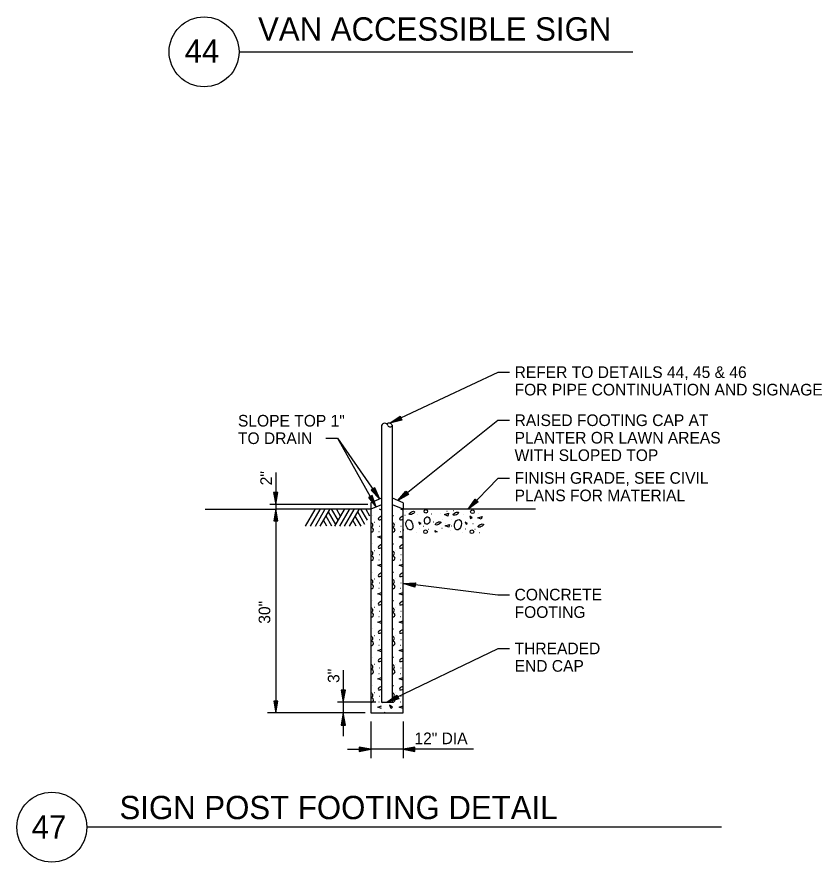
# Model space of a CAD drawing. Extents: x -121933 to -117742, y -103160 to -100084.
# Drawn here: x -118837.9 to -118423.2, y -102020 to -101584.8 of the extents above; entities that cross this region are included whole.
import ezdxf

# ---------------------------------------------------------------- set-up
doc = ezdxf.new("R2010")
doc.units = 0
for name, color, linetype in [('22', 7, 'Continuous'), ('C-TEXT', 7, 'Continuous'), ('Misc CnstDet(22)', 7, 'Continuous'), ('S-FNDN-PILE', 7, 'Continuous')]:
    doc.layers.add(name, color=color, linetype=linetype)

# ---------------------------------------------------------------- blocks, each defined once
blk = doc.blocks.new('ARROW')
at = {"layer": 'S-FNDN-PILE'}
blk.add_lwpolyline([(-0.00208, 0.00037), (-0.00208, -0.00037), (0, 0), (-0.00208, 0.00037), (-0.00198, 0), (-0.00202, -0.00027), (-0.00045, 0.00002), (-0.00202, 0.0003), (-0.00192, 0), (-0.00192, -0.00017), (-0.00083, 0.00002), (-0.00188, 0.0002), (-0.00187, -0.00012), (-0.00122, 0), (-0.00182, 0.0001), (-0.00177, -0.00005), (-0.00155, 0), (-0.00208, 0)], dxfattribs=at)

msp = doc.modelspace()

# ---------------------------------------------------------------- linework, layer by layer
at = {"layer": '22'}
for p, q in [((-118650.09, -101795.18), (-118650.09, -101937.62)), ((-118644.55, -101937.62), (-118644.55, -101795.18)), ((-118704.57, -101819.4), (-118704.57, -101850.28)), ((-118644.55, -101835.28), (-118644.55, -101819.58)), ((-118650.09, -101832.64), (-118655.6, -101834.9)), ((-118639.03, -101834.9), (-118644.55, -101832.64)), ((-118740.9, -101838.28), (-118704.79, -101838.28)), ((-118657.1, -101835.86), (-118707.57, -101835.86)), ((-118655.6, -101838.28), (-118704.79, -101838.28)), ((-118704.57, -101838.28), (-118704.57, -101943.14)), ((-118689.21, -101846.95), (-118684.27, -101838.38)), ((-118686.68, -101846.95), (-118681.77, -101838.4)), ((-118684.17, -101846.92), (-118679.29, -101838.43)), ((-118681.69, -101846.92), (-118676.76, -101838.43)), ((-118672.43, -101843.92), (-118675.65, -101838.4)), ((-118674.18, -101846.95), (-118669.22, -101838.38)), ((-118671.19, -101841.77), (-118673.16, -101838.38)), ((-118671.64, -101846.95), (-118666.69, -101838.38)), ((-118669.11, -101846.95), (-118664.18, -101838.38)), ((-118666.59, -101846.95), (-118661.65, -101838.38)), ((-118657.38, -101843.92), (-118660.57, -101838.4)), ((-118656.14, -101841.77), (-118658.09, -101838.38)), ((-118655.6, -101834.9), (-118655.6, -101838.28)), ((-118650.09, -101836.02), (-118655.6, -101838.28)), ((-118655.6, -101838.28), (-118655.6, -101943.14)), ((-118639.03, -101838.28), (-118644.55, -101836.02)), ((-118639.03, -101834.9), (-118639.03, -101838.28)), ((-118639.03, -101943.14), (-118639.03, -101838.28)), ((-118570.82, -101838.28), (-118639.03, -101838.28)), ((-118612.19, -101838.28), (-118615.51, -101838.28)), ((-118675.7, -101846.92), (-118678.7, -101841.77)), ((-118673.69, -101846.09), (-118677.44, -101839.61)), ((-118660.64, -101846.92), (-118663.63, -101841.77)), ((-118658.66, -101846.09), (-118662.38, -101839.61)), ((-118654.98, -101841.48), (-118654.86, -101841.48)), ((-118643.93, -101841.48), (-118643.82, -101841.48)), ((-118638.13, -101841.36), (-118638.03, -101841.36)), ((-118637.13, -101839.21), (-118637.03, -101839.21)), ((-118631.83, -101841.16), (-118631.73, -101841.16)), ((-118624.33, -101840.61), (-118624.23, -101840.61)), ((-118619.83, -101840.31), (-118619.73, -101840.31)), ((-118616.48, -101839.21), (-118616.38, -101839.21)), ((-118612.98, -101838.86), (-118612.88, -101838.86)), ((-118607.93, -101841.16), (-118607.83, -101841.16)), ((-118600.08, -101840.31), (-118599.98, -101840.31)), ((-118678.22, -101846.95), (-118679.97, -101843.96)), ((-118663.15, -101846.95), (-118664.91, -101843.96)), ((-118653.86, -101844.96), (-118653.75, -101844.96)), ((-118651.15, -101846.9), (-118651.03, -101846.9)), ((-118650.17, -101847.08), (-118650.09, -101847.08)), ((-118642.81, -101844.96), (-118642.7, -101844.96)), ((-118640.1, -101846.9), (-118639.98, -101846.9)), ((-118638.53, -101845.31), (-118638.43, -101845.31)), ((-118628.48, -101846.96), (-118628.38, -101846.96)), ((-118623.48, -101844.76), (-118623.38, -101844.76)), ((-118618.63, -101843.51), (-118618.53, -101843.51)), ((-118617.23, -101845.61), (-118617.13, -101845.61)), ((-118614.33, -101843.56), (-118614.23, -101843.56)), ((-118614.08, -101846.81), (-118613.98, -101846.81)), ((-118603.03, -101845.66), (-118602.93, -101845.66)), ((-118655.6, -101848.07), (-118655.53, -101848.07)), ((-118651.5, -101849.79), (-118651.39, -101849.79)), ((-118640.45, -101849.79), (-118640.34, -101849.79)), ((-118638.78, -101848.86), (-118638.68, -101848.86)), ((-118632.13, -101850.36), (-118632.03, -101850.36)), ((-118630.78, -101848.36), (-118630.68, -101848.36)), ((-118626.08, -101848.46), (-118625.98, -101848.46)), ((-118618.98, -101848.06), (-118618.88, -101848.06)), ((-118614.83, -101849.31), (-118614.73, -101849.31)), ((-118608.33, -101850.41), (-118608.23, -101850.41)), ((-118607.03, -101848.36), (-118606.93, -101848.36)), ((-118602.08, -101848.61), (-118601.98, -101848.61)), ((-118599.78, -101850.26), (-118599.68, -101850.26)), ((-118654.98, -101856.08), (-118654.86, -101856.08)), ((-118653.86, -101859.56), (-118653.75, -101859.56)), ((-118643.93, -101856.08), (-118643.82, -101856.08)), ((-118642.81, -101859.56), (-118642.7, -101859.56)), ((-118655.6, -101862.67), (-118655.53, -101862.67)), ((-118651.5, -101864.39), (-118651.39, -101864.39)), ((-118651.15, -101861.5), (-118651.03, -101861.5)), ((-118650.17, -101861.68), (-118650.09, -101861.68)), ((-118640.45, -101864.39), (-118640.34, -101864.39)), ((-118640.1, -101861.5), (-118639.98, -101861.5)), ((-118654.98, -101870.68), (-118654.86, -101870.68)), ((-118643.93, -101870.68), (-118643.82, -101870.68)), ((-118655.6, -101877.27), (-118655.53, -101877.27)), ((-118653.86, -101874.16), (-118653.75, -101874.16)), ((-118651.15, -101876.1), (-118651.03, -101876.1)), ((-118650.17, -101876.28), (-118650.09, -101876.28)), ((-118642.81, -101874.16), (-118642.7, -101874.16)), ((-118640.1, -101876.1), (-118639.98, -101876.1)), ((-118651.5, -101878.99), (-118651.39, -101878.99)), ((-118640.45, -101878.99), (-118640.34, -101878.99)), ((-118654.98, -101885.28), (-118654.86, -101885.28)), ((-118643.93, -101885.28), (-118643.82, -101885.28)), ((-118653.86, -101888.76), (-118653.75, -101888.76)), ((-118651.15, -101890.7), (-118651.03, -101890.7)), ((-118642.81, -101888.76), (-118642.7, -101888.76)), ((-118640.1, -101890.7), (-118639.98, -101890.7)), ((-118655.6, -101891.87), (-118655.53, -101891.87)), ((-118651.5, -101893.58), (-118651.39, -101893.58)), ((-118650.17, -101890.88), (-118650.09, -101890.88)), ((-118640.45, -101893.58), (-118640.34, -101893.58)), ((-118654.98, -101899.88), (-118654.86, -101899.88)), ((-118653.86, -101903.36), (-118653.75, -101903.36)), ((-118643.93, -101899.88), (-118643.82, -101899.88)), ((-118642.81, -101903.36), (-118642.7, -101903.36)), ((-118655.6, -101906.47), (-118655.53, -101906.47)), ((-118651.5, -101908.18), (-118651.39, -101908.18)), ((-118651.15, -101905.3), (-118651.03, -101905.3)), ((-118650.17, -101905.47), (-118650.09, -101905.47)), ((-118640.45, -101908.18), (-118640.34, -101908.18)), ((-118640.1, -101905.3), (-118639.98, -101905.3)), ((-118654.98, -101914.47), (-118654.86, -101914.47)), ((-118643.93, -101914.47), (-118643.82, -101914.47)), ((-118669.82, -101921.16), (-118669.82, -101955.14)), ((-118655.6, -101921.07), (-118655.53, -101921.07)), ((-118653.86, -101917.96), (-118653.75, -101917.96)), ((-118651.15, -101919.9), (-118651.03, -101919.9)), ((-118650.17, -101920.07), (-118650.09, -101920.07)), ((-118642.81, -101917.96), (-118642.7, -101917.96)), ((-118640.1, -101919.9), (-118639.98, -101919.9)), ((-118651.5, -101922.78), (-118651.39, -101922.78)), ((-118640.45, -101922.78), (-118640.34, -101922.78)), ((-118654.98, -101929.08), (-118654.86, -101929.08)), ((-118643.93, -101929.08), (-118643.82, -101929.08)), ((-118653.86, -101932.55), (-118653.75, -101932.55)), ((-118642.81, -101932.55), (-118642.7, -101932.55)), ((-118653.09, -101937.62), (-118672.82, -101937.62)), ((-118655.6, -101935.67), (-118655.53, -101935.67)), ((-118651.5, -101937.38), (-118651.39, -101937.38)), ((-118651.15, -101934.49), (-118651.03, -101934.49)), ((-118650.17, -101934.67), (-118650.09, -101934.67)), ((-118650.09, -101937.62), (-118644.55, -101937.62)), ((-118649.7, -101938.38), (-118649.58, -101938.38)), ((-118640.45, -101937.38), (-118640.34, -101937.38)), ((-118640.1, -101934.49), (-118639.98, -101934.49)), ((-118658.6, -101943.14), (-118708.92, -101943.14)), ((-118655.6, -101943.14), (-118639.03, -101943.14)), ((-118655.6, -101947.64), (-118655.6, -101966.39)), ((-118639.03, -101947.64), (-118639.03, -101966.39)), ((-118667.6, -101961.89), (-118655.6, -101961.89)), ((-118639.03, -101961.89), (-118655.6, -101961.89)), ((-118602.74, -101961.89), (-118639.03, -101961.89)), ((-118475.08, -102001.95), (-118801.89, -102001.95))]:
    msp.add_line(p, q, dxfattribs=at)
for points in [[(-118584.27, -101767.9), (-118590.27, -101767.9), (-118645.8, -101794.03)], [(-118640.6, -101790.39), (-118639.67, -101792.39), (-118645.8, -101794.03), (-118640.6, -101790.39), (-118640.41, -101791.52), (-118639.98, -101792.2), (-118644.6, -101793.42), (-118640.7, -101790.66), (-118640.59, -101791.6), (-118640.38, -101792.05), (-118643.56, -101792.93), (-118640.94, -101791.1), (-118640.58, -101791.98), (-118642.49, -101792.49), (-118640.99, -101791.46), (-118640.94, -101791.93), (-118641.59, -101792.07), (-118640.14, -101791.39)], [(-118584.27, -101792.65), (-118590.27, -101792.65), (-118641.79, -101833.77)], [(-118678.82, -101801.7), (-118672.82, -101801.7), (-118655.91, -101831.71)], [(-118672.82, -101801.7), (-118672.82, -101801.7), (-118651, -101833.01)], [(-118584.27, -101822.36), (-118590.27, -101822.36), (-118605.47, -101838.28)], [(-118653.65, -101827.24), (-118655.46, -101828.49), (-118651, -101833.01), (-118653.65, -101827.24), (-118654.38, -101828.11), (-118655.1, -101828.49), (-118651.72, -101831.87), (-118653.7, -101827.52), (-118654.27, -101828.28), (-118654.68, -101828.56), (-118652.38, -101830.92), (-118653.72, -101828.02), (-118654.47, -101828.6), (-118653.07, -101830.01), (-118653.85, -101828.36), (-118654.13, -101828.73), (-118653.64, -101829.18), (-118654.55, -101827.87)], [(-118637.58, -101829.02), (-118636.21, -101830.75), (-118641.79, -101833.77), (-118637.58, -101829.02), (-118637.13, -101830.07), (-118636.56, -101830.64), (-118640.77, -101832.89), (-118637.61, -101829.3), (-118637.29, -101830.2), (-118636.98, -101830.59), (-118639.87, -101832.17), (-118637.74, -101829.79), (-118637.19, -101830.56), (-118638.93, -101831.5), (-118637.71, -101830.15), (-118637.55, -101830.59), (-118638.15, -101830.88), (-118636.9, -101829.89)], [(-118654.96, -101831.17), (-118656.87, -101832.25), (-118652.85, -101837.15), (-118654.96, -101831.17), (-118655.77, -101831.97), (-118656.51, -101832.27), (-118653.47, -101835.95), (-118655.03, -101831.44), (-118655.67, -101832.14), (-118656.1, -101832.39), (-118654.03, -101834.95), (-118655.1, -101831.93), (-118655.9, -101832.44), (-118654.64, -101833.97), (-118655.26, -101832.26), (-118655.58, -101832.61), (-118655.13, -101833.1), (-118655.91, -101831.71)], [(-118601.95, -101833), (-118600.36, -101834.52), (-118605.47, -101838.28), (-118601.95, -101833), (-118601.36, -101833.98), (-118600.72, -101834.46), (-118604.58, -101837.27), (-118601.94, -101833.29), (-118601.5, -101834.12), (-118601.14, -101834.47), (-118603.78, -101836.44), (-118602, -101833.78), (-118601.35, -101834.47), (-118602.95, -101835.64), (-118601.92, -101834.13), (-118601.7, -101834.55), (-118602.26, -101834.92), (-118601.16, -101833.76)], [(-118650.08, -101838.68), (-118651.15, -101838.28)], [(-118639.03, -101838.68), (-118640.1, -101838.28)], [(-118617.68, -101841.06), (-118615.63, -101840.26), (-118615.93, -101841.76), (-118617.68, -101841.06)], [(-118604.73, -101841.91), (-118604.23, -101843.06), (-118603.48, -101842.66), (-118604.73, -101841.86)], [(-118600.53, -101842.66), (-118598.23, -101841.96), (-118598.78, -101843.31), (-118600.53, -101842.66)], [(-118630.88, -101844.91), (-118630.53, -101845.96), (-118629.73, -101845.66), (-118630.98, -101844.91)], [(-118617.33, -101846.81), (-118615.13, -101846.06), (-118615.53, -101847.51), (-118617.28, -101846.81)], [(-118607.08, -101845.01), (-118606.58, -101845.96), (-118605.83, -101845.61), (-118607.13, -101844.96)], [(-118622.68, -101849.16), (-118621.48, -101849.86), (-118622.23, -101850.16), (-118622.68, -101849.16)], [(-118655.6, -101852.6), (-118655.51, -101852.55), (-118655.6, -101852.5)], [(-118652.03, -101852.55), (-118650.08, -101851.96)], [(-118650.08, -101853.28), (-118652.03, -101852.55)], [(-118644.55, -101852.6), (-118644.46, -101852.55), (-118644.55, -101852.5)], [(-118640.98, -101852.55), (-118639.03, -101851.96)], [(-118639.03, -101853.28), (-118640.98, -101852.55)], [(-118655.6, -101867.2), (-118655.51, -101867.15), (-118655.6, -101867.1)], [(-118652.03, -101867.15), (-118650.08, -101866.56)], [(-118650.08, -101867.88), (-118652.03, -101867.15)], [(-118644.55, -101867.2), (-118644.46, -101867.15), (-118644.55, -101867.1)], [(-118640.98, -101867.15), (-118639.03, -101866.56)], [(-118639.03, -101867.88), (-118640.98, -101867.15)], [(-118632.7, -101876.18), (-118632.96, -101878.36), (-118639.03, -101876.52), (-118632.7, -101876.18), (-118633.13, -101877.23), (-118633.12, -101878.04), (-118637.69, -101876.63), (-118632.92, -101876.35), (-118633.32, -101877.21), (-118633.39, -101877.7), (-118636.55, -101876.77), (-118633.35, -101876.6), (-118633.52, -101877.54), (-118635.41, -101876.96), (-118633.59, -101876.88), (-118633.79, -101877.3), (-118634.42, -101877.08), (-118632.83, -101877.27)], [(-118584.27, -101882.43), (-118590.27, -101882.43), (-118632.83, -101877.27)], [(-118655.6, -101881.8), (-118655.51, -101881.75), (-118655.6, -101881.7)], [(-118652.03, -101881.75), (-118650.08, -101881.16)], [(-118650.08, -101882.47), (-118652.03, -101881.75)], [(-118644.55, -101881.8), (-118644.46, -101881.75), (-118644.55, -101881.7)], [(-118640.98, -101881.75), (-118639.03, -101881.16)], [(-118639.03, -101882.47), (-118640.98, -101881.75)], [(-118655.6, -101896.4), (-118655.51, -101896.34), (-118655.6, -101896.29)], [(-118652.03, -101896.34), (-118650.08, -101895.75)], [(-118650.08, -101897.07), (-118652.03, -101896.34)], [(-118644.55, -101896.4), (-118644.46, -101896.34), (-118644.55, -101896.29)], [(-118640.98, -101896.34), (-118639.03, -101895.75)], [(-118639.03, -101897.07), (-118640.98, -101896.34)], [(-118655.6, -101911), (-118655.51, -101910.95), (-118655.6, -101910.89)], [(-118652.03, -101910.95), (-118650.08, -101910.35)], [(-118650.08, -101911.67), (-118652.03, -101910.95)], [(-118584.27, -101910.16), (-118590.27, -101910.16), (-118647.32, -101937.62)], [(-118644.55, -101911), (-118644.46, -101910.95), (-118644.55, -101910.89)], [(-118640.98, -101910.95), (-118639.03, -101910.35)], [(-118639.03, -101911.67), (-118640.98, -101910.95)], [(-118655.6, -101925.6), (-118655.51, -101925.54), (-118655.6, -101925.49)], [(-118652.03, -101925.54), (-118650.08, -101924.95)], [(-118650.08, -101926.27), (-118652.03, -101925.54)], [(-118644.55, -101925.6), (-118644.46, -101925.54), (-118644.55, -101925.49)], [(-118640.98, -101925.54), (-118639.03, -101924.95)], [(-118639.03, -101926.27), (-118640.98, -101925.54)], [(-118642.17, -101933.92), (-118641.21, -101935.91), (-118647.32, -101937.62), (-118642.17, -101933.92), (-118641.96, -101935.04), (-118641.52, -101935.72), (-118646.13, -101936.99), (-118642.26, -101934.19), (-118642.14, -101935.13), (-118641.92, -101935.58), (-118645.09, -101936.49), (-118642.49, -101934.63), (-118642.12, -101935.51), (-118644.03, -101936.04), (-118642.54, -101934.99), (-118642.48, -101935.46), (-118643.13, -101935.61), (-118641.69, -101934.91)], [(-118652.03, -101940.15), (-118650.08, -101939.55)], [(-118650.08, -101940.87), (-118652.03, -101940.15)], [(-118648.19, -101943.14), (-118648.76, -101942.86)], [(-118648.7, -101942.92), (-118648.58, -101943.14)], [(-118645.93, -101939.26), (-118645.34, -101940.62), (-118644.46, -101940.15), (-118645.93, -101939.2)], [(-118640.98, -101940.15), (-118639.03, -101939.55)], [(-118639.03, -101940.87), (-118640.98, -101940.15)]]:
    msp.add_lwpolyline(points, dxfattribs=at)
for centre, radius in [((-118627.31, -101839.32), 0.926), ((-118603.31, -101839.57), 0.926), ((-118627.44, -101849.86), 0.926), ((-118603.59, -101849.86), 0.926), ((-118819.89, -102001.95), 18)]:
    msp.add_circle(centre, radius, dxfattribs=at)
for centre, radius, start, end in [((-118648.46, -101795.69), 1.7, 20.1247, 162.5936), ((-118646.36, -101795.89), 1.94, 21.3058, 125.2094), ((-118645.69, -101794.65), 1.26, 201.4301, 334.7726), ((-118655.64, -101846.44), 1.09, 272.0624, 87.9376), ((-118644.6, -101846.44), 1.09, 272.0624, 87.9376), ((-118655.3, -101848.92), 1.09, 254.0755, 105.9245), ((-118644.26, -101848.92), 1.09, 254.0755, 105.9245), ((-118655.64, -101861.04), 1.09, 272.0624, 87.9376), ((-118644.6, -101861.04), 1.09, 272.0624, 87.9376), ((-118655.3, -101863.52), 1.09, 254.0755, 105.9245), ((-118644.26, -101863.52), 1.09, 254.0755, 105.9245), ((-118655.64, -101875.63), 1.09, 272.0624, 87.9376), ((-118655.3, -101878.12), 1.09, 254.0755, 105.9245), ((-118644.6, -101875.63), 1.09, 272.0624, 87.9376), ((-118644.26, -101878.12), 1.09, 254.0755, 105.9245), ((-118655.64, -101890.23), 1.09, 272.0624, 87.9376), ((-118644.6, -101890.23), 1.09, 272.0624, 87.9376), ((-118655.3, -101892.72), 1.09, 254.0755, 105.9245), ((-118644.26, -101892.72), 1.09, 254.0755, 105.9245), ((-118655.64, -101904.83), 1.09, 272.0624, 87.9376), ((-118644.6, -101904.83), 1.09, 272.0624, 87.9376), ((-118655.3, -101907.32), 1.09, 254.0755, 105.9245), ((-118644.26, -101907.32), 1.09, 254.0755, 105.9245), ((-118655.64, -101919.43), 1.09, 272.0624, 87.9376), ((-118655.3, -101921.92), 1.09, 254.0755, 105.9245), ((-118644.6, -101919.43), 1.09, 272.0624, 87.9376), ((-118644.26, -101921.92), 1.09, 254.0755, 105.9245), ((-118655.64, -101934.03), 1.09, 272.0624, 87.9376), ((-118644.6, -101934.03), 1.09, 272.0624, 87.9376), ((-118655.3, -101936.52), 1.09, 254.0755, 105.9245), ((-118644.26, -101936.52), 1.09, 254.0755, 105.9245)]:
    msp.add_arc(centre, radius, start, end, dxfattribs=at)
for centre in [(-118650.26, -101842.69), (-118639.22, -101842.69), (-118650.26, -101857.29), (-118639.22, -101857.29), (-118650.26, -101871.89), (-118639.22, -101871.89), (-118650.26, -101886.49), (-118639.22, -101886.49), (-118650.26, -101901.09), (-118639.22, -101901.09), (-118650.26, -101915.69), (-118639.22, -101915.69), (-118650.26, -101930.28), (-118639.22, -101930.28)]:
    msp.add_ellipse(centre, major_axis=(-1.61, -0.76), ratio=0.393469, start_param=4.419925, end_param=7.780473, dxfattribs=at)
for centre, major_axis, ratio in [((-118634.44, -101840.17), (-1.37, -0.64), 0.393469), ((-118626.63, -101844.11), (-0.39, -1.9), 0.736889), ((-118611.84, -101840.57), (-1.37, -0.64), 0.393469), ((-118635.74, -101846.33), (-0.82, 2.58), 0.634119), ((-118621.02, -101845.58), (-1.37, -0.64), 0.393469), ((-118610.79, -101846.24), (0.58, 2.65), 0.634119), ((-118599.02, -101846.68), (-1.37, -0.64), 0.393469)]:
    msp.add_ellipse(centre, major_axis=major_axis, ratio=ratio, dxfattribs=at)
at = {"layer": 'C-TEXT'}
msp.add_lwpolyline([(-118652.85, -101833.76), (-118652.85, -101833.77), (-118652.85, -101833.76)], close=True, dxfattribs=at)
at = {"layer": 'Misc CnstDet(22)'}
msp.add_line((-118723.5, -101602.77), (-118520.63, -101602.77), dxfattribs=at)
msp.add_circle((-118741.5, -101602.77), 18, dxfattribs=at)

# ---------------------------------------------------------------- block references
at = {"layer": '22'}
for p, xscale, yscale, rotation in [((-118704.57, -101835.86), 2995.2755905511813, 2995.705082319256, -90), ((-118704.57, -101838.28), 2880, 2945.454545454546, 90), ((-118669.82, -101937.62), 2995.2755905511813, 2995.705082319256, -90), ((-118704.57, -101943.14), 2880, 2945.454545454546, -90), ((-118669.82, -101943.14), 2995.2755905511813, 2995.705082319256, 90), ((-118639.03, -101961.89), 2880, 2945.454545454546, 180)]:
    msp.add_blockref('ARROW', p, dxfattribs=dict(at, xscale=xscale, yscale=yscale, rotation=rotation))
at = {"layer": '22', "xscale": 2880, "yscale": 2945.454545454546}
msp.add_blockref('ARROW', (-118655.6, -101961.89), dxfattribs=at)

# ---------------------------------------------------------------- texts
at = {"layer": '22'}
for s, height, p in [('REFER TO DETAILS 44, 45 & 46', 6, (-118581.6, -101770.69)), ('FOR PIPE CONTINUATION AND SIGNAGE', 6, (-118581.6, -101779.69)), ('SLOPE TOP 1"', 6, (-118724.05, -101795.7)), ('RAISED FOOTING CAP AT', 6, (-118581.6, -101795.44)), ('TO DRAIN', 6, (-118724.05, -101804.7)), ('PLANTER OR LAWN AREAS', 6, (-118581.6, -101804.44)), ('WITH SLOPED TOP', 6, (-118581.6, -101813.44)), ('FINISH GRADE, SEE CIVIL', 6, (-118581.6, -101825.15)), ('PLANS FOR MATERIAL', 6, (-118581.6, -101834.15)), ('CONCRETE', 6, (-118581.6, -101885.22)), ('FOOTING', 6, (-118581.6, -101894.22)), ('THREADED', 6, (-118581.6, -101912.94)), ('END CAP', 6, (-118581.6, -101921.94)), ('12" DIA', 6, (-118633.18, -101959.24)), ('SIGN POST FOOTING DETAIL', 12, (-118785.05, -101997.85)), ('47', 12, (-118830.27, -102007.86))]:
    msp.add_text(s, height=height, dxfattribs=at).set_placement(p)
for s, p in [('2"', (-118706.55, -101825.94)), ('30"', (-118707.4, -101897.23)), ('3"', (-118671.8, -101927.71))]:
    msp.add_text(s, height=6, rotation=90, dxfattribs=at).set_placement(p)
at = {"layer": 'Misc CnstDet(22)'}
for s, p in [('VAN ACCESSIBLE SIGN', (-118713.7, -101596.97)), ('44', (-118751.49, -101608.38))]:
    msp.add_text(s, height=12, dxfattribs=at).set_placement(p)

doc.saveas('drawing.dxf')
